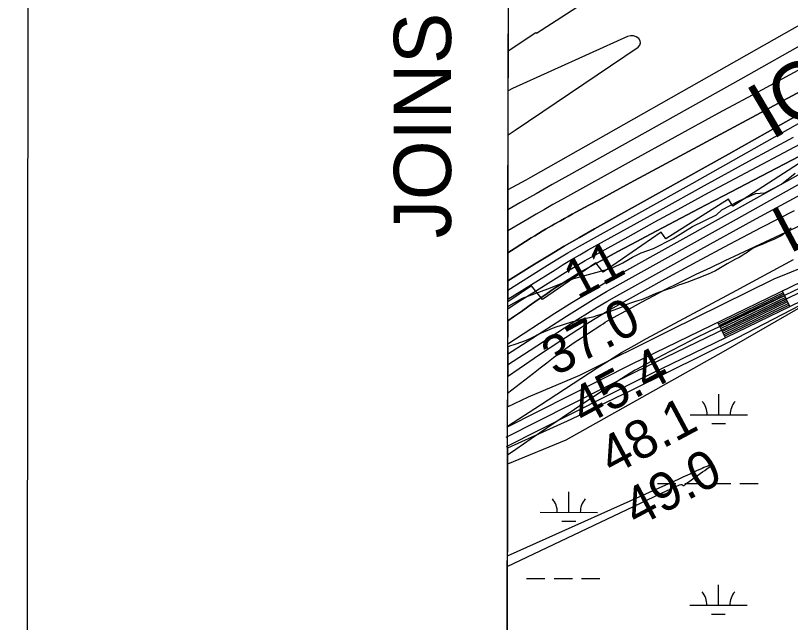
# Model space of a CAD drawing. Extents: x 3208593 to 3246461, y 812903 to 838290.
# Drawn here: x 3211927 to 3213280, y 828025 to 829085 of the extents above; entities that cross this region are included whole.
import ezdxf

# ---------------------------------------------------------------- set-up
doc = ezdxf.new("R2010")
doc.units = 0
for name, color, linetype in [('V-ANNO-SYMB', 7, 'Continuous'), ('V-ANNO-TEXT', 7, 'Continuous'), ('V-GRID-FRAM', 7, 'Continuous'), ('V-RIVR-EDGE', 7, 'Continuous'), ('V-RIVR-RANG', 7, 'Continuous'), ('V-ROAD-CNTR', 7, 'Continuous'), ('V-RRAP-RVMT', 7, 'Continuous'), ('V-RRAP-RVMT-IDEN', 7, 'Continuous'), ('V-SITE-VEGE', 7, 'Continuous'), ('V-TOPO-DPTH', 7, 'Continuous'), ('V-TOPO-MAJR', 7, 'Continuous'), ('V-TOPO-MINR', 7, 'Continuous'), ('V-TOPO-WATR', 7, 'Continuous'), ('V-TOPO-WATR-IDEN', 7, 'Continuous'), ('V-WETL-SWMP', 7, 'Continuous')]:
    doc.layers.add(name, color=color, linetype=linetype)

msp = doc.modelspace()

# ---------------------------------------------------------------- linework, layer by layer
at = {"layer": 'V-ANNO-SYMB'}
msp.add_lwpolyline([(3211927.1, 814160.7), (3245010.3, 814112.6), (3245043.6, 837029.1), (3211960.5, 837077.3), (3211927.1, 814160.7)], dxfattribs=at)
at = {"layer": 'V-GRID-FRAM'}
msp.add_lwpolyline([(3212801.6, 836513), (3244200.9, 836467.3), (3244182.3, 818280.5), (3212767.2, 818326.1), (3212801.6, 836513)], dxfattribs=at)
at = {"layer": 'V-RIVR-EDGE'}
msp.add_lwpolyline([(3212786.6, 828577.1), (3212788.7, 828577.8), (3212812.2, 828591.6), (3212856.6, 828608), (3212901.9, 828625.7), (3212940.1, 828636.5), (3212969.7, 828644.7), (3212987.5, 828652.9), (3213004.1, 828663.3), (3213019.3, 828670.7), (3213041.1, 828678.4), (3213075.5, 828695.7), (3213109.4, 828716.5), (3213150.8, 828736.8), (3213160.3, 828745.5), (3213190.8, 828761.5), (3213219.1, 828774), (3213235.2, 828775.3), (3213264.3, 828790.5), (3213288.3, 828810)], dxfattribs=at)
at = {"layer": 'V-ROAD-CNTR'}
for p, q in [((3213279.2, 828576.7), (3213266.1, 828603.7)), ((3213166.7, 828522.2), (3213153.6, 828549.2))]:
    msp.add_line(p, q, dxfattribs=at)
for points in [[(3212784, 828348.9), (3213009.9, 828462.9), (3213347.7, 828626.5), (3213606.3, 828811.3), (3213843.8, 828911.5), (3214091.9, 829054.1), (3214266.1, 829244.1), (3214392.8, 829391.9), (3214603.9, 829486.9), (3214720, 829566), (3214888.9, 829798.3), (3215094.8, 830091.2), (3215195, 830220.5), (3215374.5, 830389.5), (3215564.5, 830526.7), (3215728.1, 830700.9), (3215823.2, 830758.9), (3216097.6, 830838.1), (3216319.3, 830914.6)], [(3216324, 830900.4), (3216102.1, 830823.8), (3215829.2, 830745.1), (3215737.7, 830689.1), (3215574.5, 830515.4), (3215384.1, 830377.9), (3215206.2, 830210.4), (3215106.8, 830082.3), (3214901.1, 829789.6), (3214730.6, 829555.1), (3214611.2, 829473.7), (3214402, 829379.6), (3214277.3, 829234.1), (3214101.4, 829042.2), (3213850.5, 828898.1), (3213613.7, 828798.1), (3213355.3, 828613.6), (3213016.5, 828449.5), (3212783.7, 828331.9)], [(3214954.5, 829917.7), (3214876.7, 829807), (3214709.4, 829577), (3214596.5, 829500), (3214383.5, 829404.2), (3214254.8, 829254), (3214082.4, 829065.9), (3213837.1, 828925), (3213598.9, 828824.4), (3213340, 828639.5), (3213003.2, 828476.3), (3212784.3, 828365.8)], [(3213267.4, 828601), (3213154.9, 828546.5)], [(3213268.7, 828598.3), (3213156.2, 828543.8)], [(3213270, 828595.6), (3213157.5, 828541.1)], [(3213271.3, 828592.9), (3213158.8, 828538.4)], [(3213272.6, 828590.2), (3213160.1, 828535.7)], [(3213273.9, 828587.5), (3213161.4, 828533)], [(3213275.2, 828584.8), (3213162.7, 828530.3)], [(3213276.6, 828582.1), (3213164.1, 828527.6)], [(3213277.9, 828579.4), (3213165.4, 828524.9)]]:
    msp.add_lwpolyline(points, dxfattribs=at)
at = {"layer": 'V-RRAP-RVMT'}
for p, q in [((3212836.5, 829054.4), (3212949.4, 829127.1)), ((3212787.4, 829023.5), (3212835.8, 829055.3)), ((3212835.8, 829055.3), (3212836.5, 829054.4)), ((3212786.6, 828584.9), (3212787.4, 829023.5)), ((3213405.1, 828897.7), (3213179.4, 828752.4)), ((3213171.7, 828764.2), (3213062.4, 828694.9)), ((3213179.4, 828752.4), (3213171.7, 828764.2)), ((3213054.7, 828706.7), (3212953.4, 828636.9)), ((3213062.4, 828694.9), (3213054.7, 828706.7)), ((3212940.5, 828653), (3212847, 828589.1)), ((3212953.4, 828636.9), (3212940.5, 828653)), ((3212828.1, 828613.1), (3212786.6, 828584.9)), ((3212847, 828589.1), (3212828.1, 828613.1))]:
    msp.add_line(p, q, dxfattribs=at)
at = {"layer": 'V-SITE-VEGE'}
for p, q in [((3213275.3, 828709.3), (3213271.6, 828705.9)), ((3213281.3, 828714), (3213275.3, 828709.3)), ((3213257.1, 828696.8), (3213250.9, 828693.8)), ((3213264.9, 828701), (3213257.1, 828696.8)), ((3213268.7, 828703.7), (3213264.9, 828701)), ((3213271.6, 828705.9), (3213268.7, 828703.7)), ((3213222.7, 828682.1), (3213219, 828680.5)), ((3213230.6, 828685.1), (3213222.7, 828682.1)), ((3213238.3, 828688.8), (3213230.6, 828685.1)), ((3213243.6, 828691), (3213238.3, 828688.8)), ((3213250.9, 828693.8), (3213243.6, 828691)), ((3213200.3, 828668.7), (3213195.1, 828665.2)), ((3213202.9, 828670.3), (3213200.3, 828668.7)), ((3213209.1, 828674.7), (3213202.9, 828670.3)), ((3213212.7, 828677.1), (3213209.1, 828674.7)), ((3213216, 828679.1), (3213212.7, 828677.1)), ((3213219, 828680.5), (3213216, 828679.1)), ((3213251.9, 828625), (3213361.7, 828669.7)), ((3213184.2, 828659.5), (3213169.8, 828651.6)), ((3213190.4, 828662.5), (3213184.2, 828659.5)), ((3213195.1, 828665.2), (3213190.4, 828662.5)), ((3213163.8, 828647.8), (3213149.4, 828639.1)), ((3213169.8, 828651.6), (3213163.8, 828647.8)), ((3213136.4, 828633.4), (3213114.4, 828624.7)), ((3213141.6, 828635.5), (3213136.4, 828633.4)), ((3213149.4, 828639.1), (3213141.6, 828635.5)), ((3213389.1, 828628.5), (3213162.7, 828498)), ((3213070, 828535.8), (3213251.9, 828625)), ((3213084.7, 828614), (3213077, 828610.8)), ((3213090.6, 828616), (3213084.7, 828614)), ((3213099.4, 828619.1), (3213090.6, 828616)), ((3213114.4, 828624.7), (3213099.4, 828619.1)), ((3213057.9, 828604.3), (3213045.3, 828599.5)), ((3213066.4, 828607.1), (3213057.9, 828604.3)), ((3213071.2, 828608.6), (3213066.4, 828607.1)), ((3213077, 828610.8), (3213071.2, 828608.6)), ((3213015.2, 828587.2), (3213009.6, 828585.6)), ((3213020, 828588.8), (3213015.2, 828587.2)), ((3213032.4, 828593.5), (3213020, 828588.8)), ((3213045.3, 828599.5), (3213032.4, 828593.5)), ((3212983.1, 828574.3), (3212965.1, 828568.4)), ((3212985.8, 828575.9), (3212983.1, 828574.3)), ((3212994.5, 828580.2), (3212985.8, 828575.9)), ((3213000.9, 828582.8), (3212994.5, 828580.2)), ((3213009.6, 828585.6), (3213000.9, 828582.8)), ((3212941.7, 828560.3), (3212934.9, 828558.3)), ((3212949, 828562.9), (3212941.7, 828560.3)), ((3212956.5, 828565.5), (3212949, 828562.9)), ((3212961.5, 828567.3), (3212956.5, 828565.5)), ((3212965.1, 828568.4), (3212961.5, 828567.3)), ((3212888.3, 828546.8), (3212880.1, 828543.6)), ((3212894.5, 828548.6), (3212888.3, 828546.8)), ((3212899.8, 828550.1), (3212894.5, 828548.6)), ((3212903.2, 828550.9), (3212899.8, 828550.1)), ((3212906.7, 828552.1), (3212903.2, 828550.9)), ((3212911.8, 828553.1), (3212906.7, 828552.1)), ((3212915.3, 828554.1), (3212911.8, 828553.1)), ((3212923.6, 828555.8), (3212915.3, 828554.1)), ((3212934.9, 828558.3), (3212923.6, 828555.8)), ((3212857.5, 828535.8), (3212848.7, 828532)), ((3212861.3, 828537.3), (3212857.5, 828535.8)), ((3212870.5, 828540.6), (3212861.3, 828537.3)), ((3212880.1, 828543.6), (3212870.5, 828540.6)), ((3212912.2, 828456.9), (3213070, 828535.8)), ((3212827.3, 828521.5), (3212818.7, 828517.3)), ((3212831.9, 828524.1), (3212827.3, 828521.5)), ((3212838.8, 828527.5), (3212831.9, 828524.1)), ((3212848.7, 828532), (3212838.8, 828527.5)), ((3212786.5, 828506.3), (3212786.3, 828401.5)), ((3212791.3, 828508), (3212786.5, 828506.3)), ((3212786.5, 828506.3), (3212786.5, 828506.3)), ((3212795.6, 828509.4), (3212791.3, 828508)), ((3212799.1, 828510.7), (3212795.6, 828509.4)), ((3212810.7, 828514.4), (3212799.1, 828510.7)), ((3212818.7, 828517.3), (3212810.7, 828514.4)), ((3213162.7, 828498), (3212888.2, 828343.6)), ((3212823, 828419.1), (3212912.2, 828456.9)), ((3212786.3, 828401.5), (3212823, 828419.1)), ((3212888.2, 828343.6), (3212786.1, 828301.4)), ((3212786.1, 828301.4), (3212779.6, 824867.4))]:
    msp.add_line(p, q, dxfattribs=at)
at = {"layer": 'V-TOPO-DPTH'}
for points in [[(3214532.6, 829761), (3214517.2, 829747.8), (3214501.5, 829734.8), (3214008.1, 829342.5), (3213993.9, 829331.7), (3213979.4, 829321.2), (3213964.5, 829311.2), (3213949.4, 829301.6), (3213712.7, 829157.8), (3213578.6, 829077.4), (3213443.9, 828997.9), (3213308.3, 828920), (3213172.1, 828843.1), (3212938, 828712.6), (3212911.6, 828697.6), (3212885.3, 828682.3), (3212859.2, 828666.7), (3212833.3, 828650.7), (3212786.7, 828621.7)], [(3212786.8, 828670.8), (3212786.7, 828621.7), (3212833.3, 828650.7), (3212859.2, 828666.7), (3212885.3, 828682.3), (3212911.6, 828697.6), (3212938, 828712.6), (3213172.1, 828843.1), (3213308.3, 828920), (3213443.9, 828997.9), (3213578.6, 829077.4), (3213712.7, 829157.8), (3213949.4, 829301.6), (3213964.5, 829311.2), (3213979.4, 829321.2), (3213993.9, 829331.7), (3214008.1, 829342.5), (3214501.5, 829734.8), (3214517.2, 829747.8), (3214532.6, 829761)], [(3212786.6, 828551.6), (3212786.4, 828493.6), (3212889, 828559.9), (3212912.2, 828574.5), (3212935.5, 828588.9), (3212959.2, 828602.8), (3212983.1, 828616.4), (3213186.2, 828729.4), (3213311.4, 828799.8), (3213436.2, 828871.1), (3213560.2, 828943.5), (3213683.8, 829016.8), (3214010.4, 829212.5), (3214029.4, 829224.4), (3214048, 829236.9), (3214066.1, 829250.1), (3214083.8, 829263.9), (3214604.5, 829686.5)], [(3213307, 828996.7), (3213230.6, 828955.6), (3213154.3, 828914.3), (3213078.3, 828872.6), (3213002.3, 828830.7), (3212880.3, 828763.1), (3212865.5, 828754.8), (3212850.8, 828746.4), (3212836, 828738), (3212821.4, 828729.4), (3212786.9, 828709.2), (3212788.2, 829398.7)], [(3213542.3, 829084), (3213000.4, 828792.6), (3212982.4, 828782.9), (3212964.3, 828773.2), (3212946.3, 828763.4), (3212928.2, 828753.7), (3212905.6, 828741.5), (3212898.9, 828737.9), (3212892.2, 828734.2), (3212885.4, 828730.5), (3212878.7, 828726.8), (3212867.9, 828720.8), (3212864, 828718.6), (3212862.7, 828717.8), (3212852.7, 828711.9), (3212846.4, 828708.2), (3212840.1, 828704.4), (3212833.8, 828700.5), (3212827.6, 828696.6), (3212799.3, 828678.8), (3212786.8, 828670.8)], [(3212786.9, 828709.2), (3212786.8, 828670.8), (3212799.3, 828678.8), (3212827.6, 828696.6), (3212833.8, 828700.5), (3212840.1, 828704.4), (3212846.4, 828708.2), (3212852.7, 828711.9), (3212862.7, 828717.8), (3212864, 828718.6), (3212867.9, 828720.8), (3212878.7, 828726.8), (3212885.4, 828730.5), (3212892.2, 828734.2), (3212898.9, 828737.9), (3212905.6, 828741.5), (3212928.2, 828753.7), (3212946.3, 828763.4), (3212964.3, 828773.2), (3212982.4, 828782.9), (3213000.4, 828792.6), (3213542.3, 829084)], [(3213307, 828996.7), (3213230.6, 828955.6), (3213154.3, 828914.3), (3213078.3, 828872.6), (3213002.3, 828830.7), (3212880.3, 828763.1), (3212865.5, 828754.8), (3212850.8, 828746.4), (3212836, 828738), (3212821.4, 828729.4), (3212786.9, 828709.2)], [(3213534.4, 828964.2), (3213163.5, 828770.4), (3213131.6, 828753.7), (3213099.6, 828736.9), (3213067.7, 828720.1), (3213035.8, 828703.3), (3213003.1, 828686), (3212987.6, 828677.7), (3212972.1, 828669.4), (3212956.7, 828660.9), (3212941.3, 828652.4), (3212916.4, 828638.6), (3212913.5, 828636.9), (3212910.6, 828635.2), (3212907.7, 828633.5), (3212904.8, 828631.7), (3212888.2, 828621.3), (3212877.1, 828614.3), (3212866.1, 828607.1), (3212855.2, 828599.8), (3212844.3, 828592.3), (3212838.1, 828587.9), (3212824.2, 828578.1), (3212810.3, 828568.4), (3212796.4, 828558.6), (3212786.6, 828551.6), (3212786.6, 828589.7)], [(3213534.4, 828964.2), (3213163.5, 828770.4), (3213131.6, 828753.7), (3213099.6, 828736.9), (3213067.7, 828720.1), (3213035.8, 828703.3), (3213003.1, 828686), (3212987.6, 828677.7), (3212972.1, 828669.4), (3212956.7, 828660.9), (3212941.3, 828652.4), (3212916.4, 828638.6), (3212913.5, 828636.9), (3212910.6, 828635.2), (3212907.7, 828633.5), (3212904.8, 828631.7), (3212888.2, 828621.3), (3212877.1, 828614.3), (3212866.1, 828607.1), (3212855.2, 828599.8), (3212844.3, 828592.3), (3212838.1, 828587.9), (3212824.2, 828578.1), (3212810.3, 828568.4), (3212796.4, 828558.6), (3212786.6, 828551.6)], [(3212786.7, 828621.7), (3212786.6, 828589.7), (3212869.1, 828641.2), (3212883.5, 828650.1), (3212897.9, 828658.8), (3212912.5, 828667.2), (3212927.2, 828675.6), (3213052.4, 828745.3), (3213129.9, 828788.1), (3213207.6, 828830.7), (3213285.5, 828872.8)], [(3212786.6, 828589.7), (3212869.1, 828641.2), (3212883.5, 828650.1), (3212897.9, 828658.8), (3212912.5, 828667.2), (3212927.2, 828675.6), (3213052.4, 828745.3), (3213129.9, 828788.1), (3213207.6, 828830.7), (3213285.5, 828872.8)]]:
    msp.add_lwpolyline(points, dxfattribs=at)
at = {"layer": 'V-TOPO-MAJR'}
for points in [[(3214568.4, 830031.2), (3214512.7, 829963), (3214502.8, 829951.2), (3214492.8, 829939.5), (3214482.6, 829927.9), (3214472.3, 829916.5), (3214377.1, 829813.6), (3214317.9, 829752.1), (3214257, 829692.2), (3214193.8, 829634.9), (3214129, 829579.3), (3213937.2, 829421.3), (3213925.2, 829411.9), (3213913, 829402.8), (3213900.4, 829394.2), (3213887.6, 829385.9), (3213675.5, 829256.1), (3213556, 829183.9), (3213435.9, 829112.7), (3213315.1, 829042.8), (3213193.6, 828974), (3212892.6, 828805.6), (3212864.3, 828789.7), (3212836.1, 828773.7)], [(3212836.1, 828773.7), (3212807.9, 828757.7), (3212786.9, 828745.8)], [(3212786.3, 828425.5), (3212831.3, 828460.4), (3212843.1, 828469.5), (3212854.9, 828478.6), (3212866.7, 828487.6), (3212878.6, 828496.5), (3212890.6, 828505.3), (3212902.8, 828513.9), (3212915.1, 828522.3), (3212927.5, 828530.5), (3212949, 828544.4), (3212952.9, 828546.9), (3212956.8, 828549.3), (3212960.8, 828551.6), (3212964.8, 828553.9), (3212998.9, 828572.9), (3213020, 828584.5), (3213041.3, 828595.8), (3213062.7, 828606.9), (3213084.3, 828617.7), (3213090.9, 828621), (3213115.8, 828633.2), (3213140.9, 828645.3), (3213166, 828657.3), (3213191.1, 828669.1), (3213370.4, 828752.9)]]:
    msp.add_lwpolyline(points, dxfattribs=at)
at = {"layer": 'V-TOPO-MINR'}
for points in [[(3212786.7, 828605.6), (3212851.2, 828646), (3212871.3, 828658.4), (3212891.6, 828670.5), (3212912.1, 828682.4), (3212932.6, 828694.1), (3213108.5, 828792), (3213216.9, 828852.9), (3213325, 828914.2), (3213432.7, 828976.2), (3213540.1, 829038.8), (3213944.4, 829275.8), (3213968.4, 829290.4), (3213992.1, 829305.6), (3214015.3, 829321.7), (3214038, 829338.2), (3214192.2, 829454.6), (3214263.2, 829509.5), (3214333.3, 829565.7), (3214401.8, 829623.6), (3214469.5, 829682.7), (3214598.7, 829798.4)], [(3212786.7, 828621.7), (3212833.3, 828650.7), (3212859.2, 828666.7), (3212885.3, 828682.3), (3212911.6, 828697.6), (3212938, 828712.6), (3213172.1, 828843.1), (3213308.3, 828920), (3213443.9, 828997.9), (3213578.6, 829077.4), (3213712.7, 829157.8), (3213949.4, 829301.6), (3213964.5, 829311.2), (3213979.4, 829321.2), (3213993.9, 829331.7), (3214008.1, 829342.5), (3214501.5, 829734.8), (3214517.2, 829747.8), (3214532.6, 829761)], [(3212786.4, 828493.6), (3212889, 828559.9), (3212912.2, 828574.5), (3212935.5, 828588.9), (3212959.2, 828602.8), (3212983.1, 828616.4), (3213186.2, 828729.4), (3213311.4, 828799.8), (3213436.2, 828871.1), (3213560.2, 828943.5), (3213683.8, 829016.8), (3214010.4, 829212.5), (3214029.4, 829224.4), (3214048, 829236.9), (3214066.1, 829250.1), (3214083.8, 829263.9), (3214604.5, 829686.5)], [(3212786.5, 828511.6), (3212869, 828565), (3212898.6, 828583.7), (3212928.5, 828602.1), (3212958.7, 828619.9), (3212989.2, 828637.2), (3213330.5, 828827.2), (3213450.3, 828894.6), (3213569.7, 828962.8), (3213688.3, 829032.1), (3213806.6, 829102.2), (3214012.7, 829225.8), (3214027.3, 829235), (3214041.7, 829244.6), (3214055.6, 829254.8), (3214069.2, 829265.4), (3214412.8, 829543.5), (3214452.7, 829576.7), (3214492, 829610.7), (3214530.3, 829645.7)], [(3213751.9, 829328.3), (3213714.5, 829306.4), (3213676.9, 829284.8), (3212826.1, 828802.2), (3212822, 828799.9), (3212817.9, 828797.7), (3212787, 828780.5)], [(3212786.8, 828670.8), (3212799.3, 828678.8), (3212827.6, 828696.6), (3212833.8, 828700.5), (3212840.1, 828704.4), (3212846.4, 828708.2), (3212852.7, 828711.9), (3212862.7, 828717.8), (3212864, 828718.6), (3212867.9, 828720.8), (3212878.7, 828726.8), (3212885.4, 828730.5), (3212892.2, 828734.2), (3212898.9, 828737.9), (3212905.6, 828741.5), (3212928.2, 828753.7), (3212946.3, 828763.4), (3212964.3, 828773.2), (3212982.4, 828782.9), (3213000.4, 828792.6), (3213542.3, 829084)], [(3212787.2, 828876.8), (3212791, 828879.2), (3212799.6, 828884.8), (3213014.4, 829030.1), (3213017.3, 829033.6), (3213018.6, 829037.3), (3213017.9, 829041.2), (3213015.6, 829045.1), (3213011, 829048.1), (3213006.1, 829049.8), (3213001, 829049.7), (3212995.7, 829048.4), (3212795.1, 828957.5), (3212787.3, 828953.8)], [(3213307, 828996.7), (3213230.6, 828955.6), (3213154.3, 828914.3), (3213078.3, 828872.6), (3213002.3, 828830.7), (3212880.3, 828763.1), (3212865.5, 828754.8), (3212850.8, 828746.4), (3212836, 828738), (3212821.4, 828729.4), (3212786.9, 828709.2)], [(3212786.6, 828589.7), (3212869.1, 828641.2), (3212883.5, 828650.1), (3212897.9, 828658.8), (3212912.5, 828667.2), (3212927.2, 828675.6), (3213052.4, 828745.3), (3213129.9, 828788.1), (3213207.6, 828830.7), (3213285.5, 828872.8)], [(3212786.6, 828572.9), (3212803.3, 828583.8), (3212836.8, 828605.1), (3212887, 828636.5), (3212895.6, 828641.8), (3212904.3, 828647), (3212913, 828652.1), (3212921.8, 828657.1), (3212996.9, 828698.8), (3213043.3, 828724.5), (3213089.8, 828750), (3213136.5, 828775.2), (3213183.4, 828800.2), (3213306.6, 828865.6)], [(3212786.4, 828475.1), (3212825.6, 828500.8), (3212909, 828554.7), (3212925.7, 828565.3), (3212942.6, 828575.7), (3212959.7, 828585.7), (3212977, 828595.6), (3213123.6, 828677.1), (3213214.5, 828727), (3213305.7, 828776.4)], [(3212786.4, 828454.8), (3212806.4, 828468.8), (3212841.9, 828492.8), (3212877.6, 828516.4), (3212929, 828549.6), (3212939.3, 828556.1), (3212949.7, 828562.5), (3212960.3, 828568.7), (3212970.9, 828574.7), (3213061.2, 828625), (3213117.3, 828655.7), (3213173.6, 828686), (3213230.3, 828715.5), (3213287.2, 828744.6)], [(3212786.1, 828317.9), (3212800.6, 828327.9), (3212827.6, 828346.4), (3212854.7, 828364.9), (3212881.8, 828383.3), (3212902.9, 828397.6), (3212919.5, 828408.7), (3212936.1, 828419.7), (3212952.9, 828430.7), (3212969.6, 828441.5), (3212993.8, 828457), (3212998.6, 828460), (3213003.3, 828462.9), (3213008.1, 828465.6), (3213013, 828468.3), (3213047.8, 828487), (3213070.2, 828498.8), (3213092.6, 828510.5), (3213115.2, 828521.9), (3213137.9, 828533.1), (3213139.1, 828533.7), (3213162.5, 828545), (3213185.8, 828556.3), (3213209.3, 828567.5), (3213232.7, 828578.7), (3213426.6, 828671.1)], [(3212786.2, 828368), (3212843.7, 828405), (3212942.9, 828469.9), (3212964, 828483.3), (3212985.3, 828496.4), (3213007, 828508.9), (3213028.8, 828521), (3213185.2, 828605), (3213285.6, 828658.7)], [(3213072.5, 828259), (3213076.4, 828260.7), (3213080.2, 828262.5), (3213086.6, 828265.3), (3213088.7, 828265.9), (3213090.4, 828265.9), (3213091, 828265.6), (3213091.8, 828264.8), (3213092.5, 828264.5), (3213094.2, 828264.5), (3213097.1, 828266.4), (3213099, 828268.3), (3213100.2, 828269.3), (3213100.7, 828269.6), (3213122.8, 828285.1), (3213126.7, 828287.9), (3213130.6, 828290.6), (3213134.4, 828293.5), (3213138.3, 828296.3), (3213140.1, 828297.7), (3213140.5, 828298.5), (3213140.4, 828299.1), (3213139.9, 828299.4), (3213139.1, 828299.6), (3213135.8, 828298.3), (3213132.4, 828297), (3213129.1, 828295.6), (3213125.8, 828294.1), (3213116.4, 828289.7), (3213108.4, 828286), (3213100.4, 828282.3), (3213092.4, 828278.7), (3213084.4, 828275), (3212785.8, 828140.7)], [(3212785.7, 828122.9), (3213064.9, 828255.4), (3213068.7, 828257.2), (3213072.5, 828259)]]:
    msp.add_lwpolyline(points, dxfattribs=at)
at = {"layer": 'V-TOPO-WATR'}
msp.add_lwpolyline([(3212786.6, 828551.6), (3212796.4, 828558.6), (3212810.3, 828568.4), (3212824.2, 828578.1), (3212838.1, 828587.9), (3212844.3, 828592.3), (3212855.2, 828599.8), (3212866.1, 828607.1), (3212877.1, 828614.3), (3212888.2, 828621.3), (3212904.8, 828631.7), (3212907.7, 828633.5), (3212910.6, 828635.2), (3212913.5, 828636.9), (3212916.4, 828638.6), (3212941.3, 828652.4), (3212956.7, 828660.9), (3212972.1, 828669.4), (3212987.6, 828677.7), (3213003.1, 828686), (3213035.8, 828703.3), (3213067.7, 828720.1), (3213099.6, 828736.9), (3213131.6, 828753.7), (3213163.5, 828770.4), (3213534.4, 828964.2)], dxfattribs=at)
at = {"layer": 'V-WETL-SWMP'}
for p, q in [((3213324.5, 828593.2), (3213187.9, 828522)), ((3213187.9, 828522), (3213003.1, 828430.9)), ((3213003.1, 828430.9), (3212896.8, 828379.6)), ((3213154.9, 828387.7), (3213154.9, 828423.7)), ((3213104.9, 828387.8), (3213204.9, 828387.6)), ((3212896.8, 828379.6), (3212786.1, 828329.4)), ((3213142.8, 828372.3), (3213166.8, 828372.3)), ((3212786.1, 828329.4), (3212776.8, 823382.4)), ((3213047.9, 828267.8), (3213079.9, 828267.8)), ((3213095.9, 828267.7), (3213127.9, 828267.7)), ((3213143.9, 828267.7), (3213175.9, 828267.6)), ((3213191.9, 828267.6), (3213223.9, 828267.5)), ((3212893.2, 828217.3), (3212893.2, 828253.3)), ((3212843.2, 828217.4), (3212943.2, 828217.2)), ((3212881.2, 828201.9), (3212905.2, 828201.8)), ((3212819.6, 828102), (3212851.6, 828101.9)), ((3212867.6, 828101.9), (3212899.6, 828101.8)), ((3212915.6, 828101.8), (3212947.6, 828101.8)), ((3213154.4, 828055), (3213154.4, 828091)), ((3213104.4, 828055.1), (3213204.4, 828055)), ((3213142.4, 828039.6), (3213166.4, 828039.6))]:
    msp.add_line(p, q, dxfattribs=at)
for centre, start, end in [((3213099.6, 828388.3), 359.1448, 40.6885), ((3213210.1, 828388.1), 139.1448, 180.6885), ((3212837.9, 828217.8), 359.1448, 40.6885), ((3212948.4, 828217.7), 139.1448, 180.6885), ((3213099.1, 828055.6), 359.1448, 40.6885), ((3213209.6, 828055.4), 139.1448, 180.6885)]:
    msp.add_arc(centre, 35.2, start, end, dxfattribs=at)

# ---------------------------------------------------------------- texts
at = {"layer": 'V-ANNO-TEXT'}
msp.add_text('JOINS SHEET 14', height=100, rotation=90, dxfattribs=at).set_placement((3212687.6, 828696))
at = {"layer": 'V-RIVR-RANG'}
for s, rotation, p in [('11', 28.5051, (3212908.4, 828588.4)), ('37.0', 28.1383, (3212869.7, 828454.4)), ('45.4', 28.1383, (3212919.6, 828367.7)), ('48.1', 28.1383, (3212969.1, 828280.8)), ('49.0', 28.1383, (3213011.8, 828190.2))]:
    msp.add_text(s, height=67, rotation=rotation, dxfattribs=at).set_placement(p)
at = {"layer": 'V-RRAP-RVMT-IDEN'}
msp.add_text('IOWA ', height=100, rotation=30.4153, dxfattribs=at).set_placement((3213246.3, 828866.2))
at = {"layer": 'V-TOPO-WATR-IDEN'}
msp.add_text('L.W.R.P.', height=83, rotation=27.7495, dxfattribs=at).set_placement((3213279.1, 828668.4))

doc.saveas('drawing.dxf')
